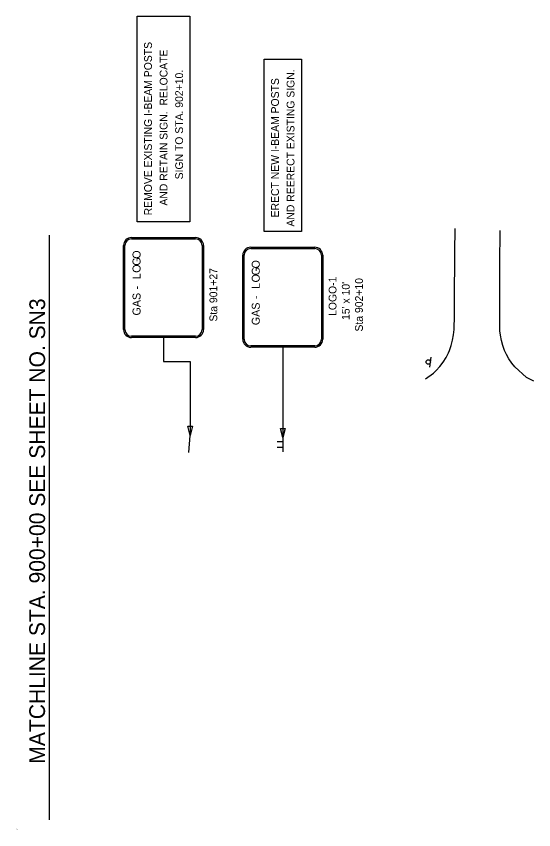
# Model space of a CAD drawing. Extents: x 1738774 to 1740359, y 1166808 to 1167650.
# Drawn here: x 1738774 to 1739240, y 1166918 to 1167650 of the extents above; entities that cross this region are included whole.
import ezdxf

# ---------------------------------------------------------------- set-up
doc = ezdxf.new("R2010")
doc.units = 0
for name, color, linetype in [('Default', 7, 'Continuous'), ('RD_EX_Road', 7, 'Continuous'), ('RD_SHT_MatchLine', 7, 'Continuous'), ('RD_SHT_TX', 7, 'Continuous'), ('SN_P_Signs', 7, 'Continuous')]:
    doc.layers.add(name, color=color, linetype=linetype)

msp = doc.modelspace()

# ---------------------------------------------------------------- linework, layer by layer
at = {"layer": 'RD_EX_Road'}
for points in [[(1739142.36, 1167323.99), (1739149.66, 1167329.21), (1739152.03, 1167331.53), (1739155.27, 1167335.17), (1739158.2, 1167339.06), (1739160.8, 1167343.17), (1739163.07, 1167347.48), (1739163.87, 1167349.39), (1739165.5, 1167354), (1739166.76, 1167358.72), (1739167.63, 1167363.53), (1739168.11, 1167368.4), (1739168.35, 1167381.27), (1739168.49, 1167402.92), (1739168.59, 1167428.45), (1739168.63, 1167438), (1739169.01, 1167459.32)], [(1739239.81, 1167321.92), (1739237.35, 1167323.08), (1739233.4, 1167325.28), (1739222.86, 1167334.63), (1739219.98, 1167338.16), (1739217.42, 1167341.92), (1739215.2, 1167345.89), (1739213.62, 1167349.33), (1739211.95, 1167353.87), (1739210.66, 1167358.54), (1739209.75, 1167363.29), (1739209.3, 1167367.22), (1739209.25, 1167383.03), (1739209.17, 1167411.99), (1739209.29, 1167435.96), (1739209.59, 1167448.96), (1739209.49, 1167457.47)]]:
    msp.add_lwpolyline(points, dxfattribs=at)
at = {"layer": 'RD_SHT_MatchLine'}
msp.add_lwpolyline([(1738803.73, 1166927.13), (1738803.73, 1167194.04), (1738803.73, 1167453.23)], dxfattribs=at)
at = {"layer": 'SN_P_Signs'}
for p, q in [((1738882.57, 1167465.21), (1738882.57, 1167650.23)), ((1738882.57, 1167650.23), (1738930.19, 1167650.23)), ((1738930.19, 1167650.23), (1738930.19, 1167465.21)), ((1738996.93, 1167456.5), (1738996.93, 1167611.52)), ((1738996.93, 1167611.52), (1739030.54, 1167611.52)), ((1739030.54, 1167611.52), (1739030.54, 1167456.5)), ((1738930.19, 1167465.21), (1738882.57, 1167465.21)), ((1739030.54, 1167456.5), (1738996.93, 1167456.5)), ((1738906.38, 1167361.1), (1738906.38, 1167339.64)), ((1739013.73, 1167352.39), (1739013.73, 1167271.18)), ((1739146.26, 1167334.39), (1739147.33, 1167343.33)), ((1738906.38, 1167339.64), (1738930.34, 1167339.64)), ((1738930.34, 1167339.64), (1738930.34, 1167273.05)), ((1738929.13, 1167257.62), (1738930.34, 1167273.05)), ((1739013.73, 1167271.18), (1739013.73, 1167258.14)), ((1739013.73, 1167267.27), (1739008.74, 1167267.27)), ((1739013.73, 1167262.25), (1739008.74, 1167262.25))]:
    msp.add_line(p, q, dxfattribs=at)
for points in [[(1738877.58, 1167451.1), (1738935.18, 1167451.1)], [(1738877.58, 1167449.9), (1738935.18, 1167449.9)], [(1738870.38, 1167368.3), (1738870.38, 1167443.9)], [(1738871.58, 1167368.3), (1738871.58, 1167443.9)], [(1738941.18, 1167443.9), (1738941.18, 1167368.3)], [(1738942.38, 1167443.9), (1738942.38, 1167368.3)], [(1738984.93, 1167442.39), (1739042.53, 1167442.39)], [(1738984.93, 1167441.19), (1739042.53, 1167441.19)], [(1738977.73, 1167359.59), (1738977.73, 1167435.19)], [(1738978.93, 1167359.59), (1738978.93, 1167435.19)], [(1739048.53, 1167435.19), (1739048.53, 1167359.59)], [(1739049.73, 1167435.19), (1739049.73, 1167359.59)], [(1738935.18, 1167362.3), (1738877.58, 1167362.3)], [(1738935.18, 1167361.1), (1738877.58, 1167361.1)], [(1739042.53, 1167353.59), (1738984.93, 1167353.59)], [(1739042.53, 1167352.39), (1738984.93, 1167352.39)]]:
    msp.add_lwpolyline(points, dxfattribs=at)
for points in [[(1738932.4, 1167281.26), (1738930.34, 1167273.05), (1738928.29, 1167281.26)], [(1739015.79, 1167279.38), (1739013.73, 1167271.18), (1739011.68, 1167279.38)]]:
    msp.add_lwpolyline(points, close=True, dxfattribs=at)
msp.add_circle((1739144.79, 1167339.12), 2, dxfattribs=at)
for centre, radius, start, end in [((1738877.58, 1167443.9), 7.2, 90, 180), ((1738877.58, 1167443.9), 6, 90, 180), ((1738935.18, 1167443.9), 7.2, 0, 90), ((1738935.18, 1167443.9), 6, 0, 90), ((1738984.93, 1167435.19), 7.2, 90, 180), ((1738984.93, 1167435.19), 6, 90, 180), ((1739042.53, 1167435.19), 7.2, 0, 90), ((1739042.53, 1167435.19), 6, 0, 90), ((1738877.58, 1167368.3), 7.2, 180, 270), ((1738877.58, 1167368.3), 6, 180, 270), ((1738935.18, 1167368.3), 6, 270, 0), ((1738935.18, 1167368.3), 7.2, 270, 0), ((1738984.93, 1167359.59), 7.2, 180, 270), ((1738984.93, 1167359.59), 6, 180, 270), ((1739042.53, 1167359.59), 6, 270, 0), ((1739042.53, 1167359.59), 7.2, 270, 0)]:
    msp.add_arc(centre, radius, start, end, dxfattribs=at)

# ---------------------------------------------------------------- texts
at = {"layer": 'Default'}
for s, height, p in [('Angle:  16.0848', 0.2083, (1738773.73, 1166918.56)), ('Align: A_I85', 0.2083, (1738773.73, 1166918.29)), ('Sheet: 4', 0.208, (1738773.73, 1166918.83))]:
    msp.add_text(s, height=height, dxfattribs=at).set_placement(p)
at = {"layer": 'RD_SHT_TX'}
msp.add_text('MATCHLINE STA. 900+00 SEE SHEET NO. SN3', height=14.1726, rotation=89.98556, dxfattribs=at).set_placement((1738799.61, 1166977.67))
at = {"layer": 'SN_P_Signs'}
for s, height, rotation, p in [('REMOVE EXISTING I-BEAM POSTS', 6.9998, 90.00008, (1738895.93, 1167471.1)), ('AND RETAIN SIGN.  RELOCATE', 6.9998, 90.00008, (1738909.93, 1167479.84)), ('SIGN TO STA. 902+10.', 6.9998, 90.00008, (1738923.93, 1167503.45)), ('AND REERECT EXISTING SIGN.', 6.9998, 90.00008, (1739024.29, 1167460.98)), ('ERECT NEW I-BEAM POSTS', 6.9998, 90.00008, (1739010.29, 1167469.23)), ('O', 7.2, 90, (1738885.68, 1167432.01)), ('O', 7.2, 90, (1738885.68, 1167432.01)), ('G', 7.2, 90, (1738885.68, 1167425.82)), ('G', 7.2, 90, (1738885.68, 1167425.82)), ('O', 7.2, 90, (1738993.03, 1167423.3)), ('O', 7.2, 90, (1738993.03, 1167423.3)), ('O', 7.2, 90, (1738885.68, 1167419.41)), ('O', 7.2, 90, (1738885.68, 1167419.41)), ('Sta 901+27', 7, 90.00008, (1738954.75, 1167375.5)), ('G', 7.2, 90, (1738993.03, 1167417.11)), ('G', 7.2, 90, (1738993.03, 1167417.11)), ('L', 7.2, 90, (1738885.68, 1167413.67)), ('L', 7.2, 90, (1738885.68, 1167413.67)), ('O', 7.2, 90, (1738993.03, 1167410.7)), ('O', 7.2, 90, (1738993.03, 1167410.7)), ('LOGO-1', 7, 90.00008, (1739062.11, 1167380.57)), ('L', 7.2, 90, (1738993.03, 1167404.96)), ('L', 7.2, 90, (1738993.03, 1167404.96)), ("15' x 10'", 7, 90.00008, (1739074.01, 1167376.94)), ('Sta 902+10', 7, 90.00008, (1739085.91, 1167366.52)), ('GAS', 7.2, 90, (1738885.68, 1167380.98)), ('-', 7.2, 90, (1738885.68, 1167404.3)), ('-', 7.2, 90, (1738885.68, 1167404.3)), ('-', 7.2, 90, (1738993.03, 1167395.59)), ('-', 7.2, 90, (1738993.03, 1167395.59)), ('GAS', 7.2, 90, (1738993.03, 1167372.27))]:
    msp.add_text(s, height=height, rotation=rotation, dxfattribs=at).set_placement(p)

doc.saveas('drawing.dxf')
